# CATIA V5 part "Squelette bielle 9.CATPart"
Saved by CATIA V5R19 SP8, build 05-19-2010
Part number: Squelette bielle 9
Publications: "Droite EF (Bielle 9)", "Droite E (bielle 9)", "Droite F (bielle 9)", "Point.3", "Point.4", "Plan.3", "Plan.4", "Droite.4", "Plan.6"
Bounding box of the stored display mesh (mm): x -43 to 32, y -103 to 35, z -50 to 50
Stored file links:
  G:\EU_thinkMotion\CFAO_2010\MMS_groupe3\MMS_groupe3\A reprendre\lpastor\lpastor\Squelette bielle 9.CATPart
  C:\Users\Loïc\Documents\IFMA\Cours 2A\CFAO\Thinkmotion\Fourche avant.CATProduct
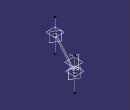
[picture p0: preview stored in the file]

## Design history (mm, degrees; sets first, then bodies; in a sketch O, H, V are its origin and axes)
Set1
  Point1 "E": linked copy from another document
  Point2 "F": linked copy from another document
Set2 "Set géométrique bielle 9"
  Line1 "Droite E (bielle 9)": type PtDir, RefPoint Point1, Direction xy-plane, Start -50, End 50
  Line2 "Droite F (bielle 9)": type PtDir, RefPoint Point2, Direction xy-plane, Start -50, End 50
  Line3 "Droite EF (Bielle 9)": type PtPt, FirstPoint Point1, SecondPoint Point2
  Point3: type OnCurve, Support Line1, RefPoint Point1, Length 9
  Point4: type OnCurve, Support Line2, RefPoint Point2, Length 9
  Plane1: type Normal, Curve Line3, RefPoint Point1
  Plane2: type Normal, Curve Line3, RefPoint Point2
  Plane3: type Offset, RefPlane Plane1, Offset 4
  Plane4: type Offset, RefPlane Plane2, Offset 4, reversed
  Plane5: type Normal, Curve Line1, RefPoint Point3
  Plane6: type Normal, Curve Line2, RefPoint Point4
  Line4: type PtPt, FirstPoint Point3, SecondPoint Point4
Body1 (main body)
